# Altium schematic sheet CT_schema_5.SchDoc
size 278 x 170 mm
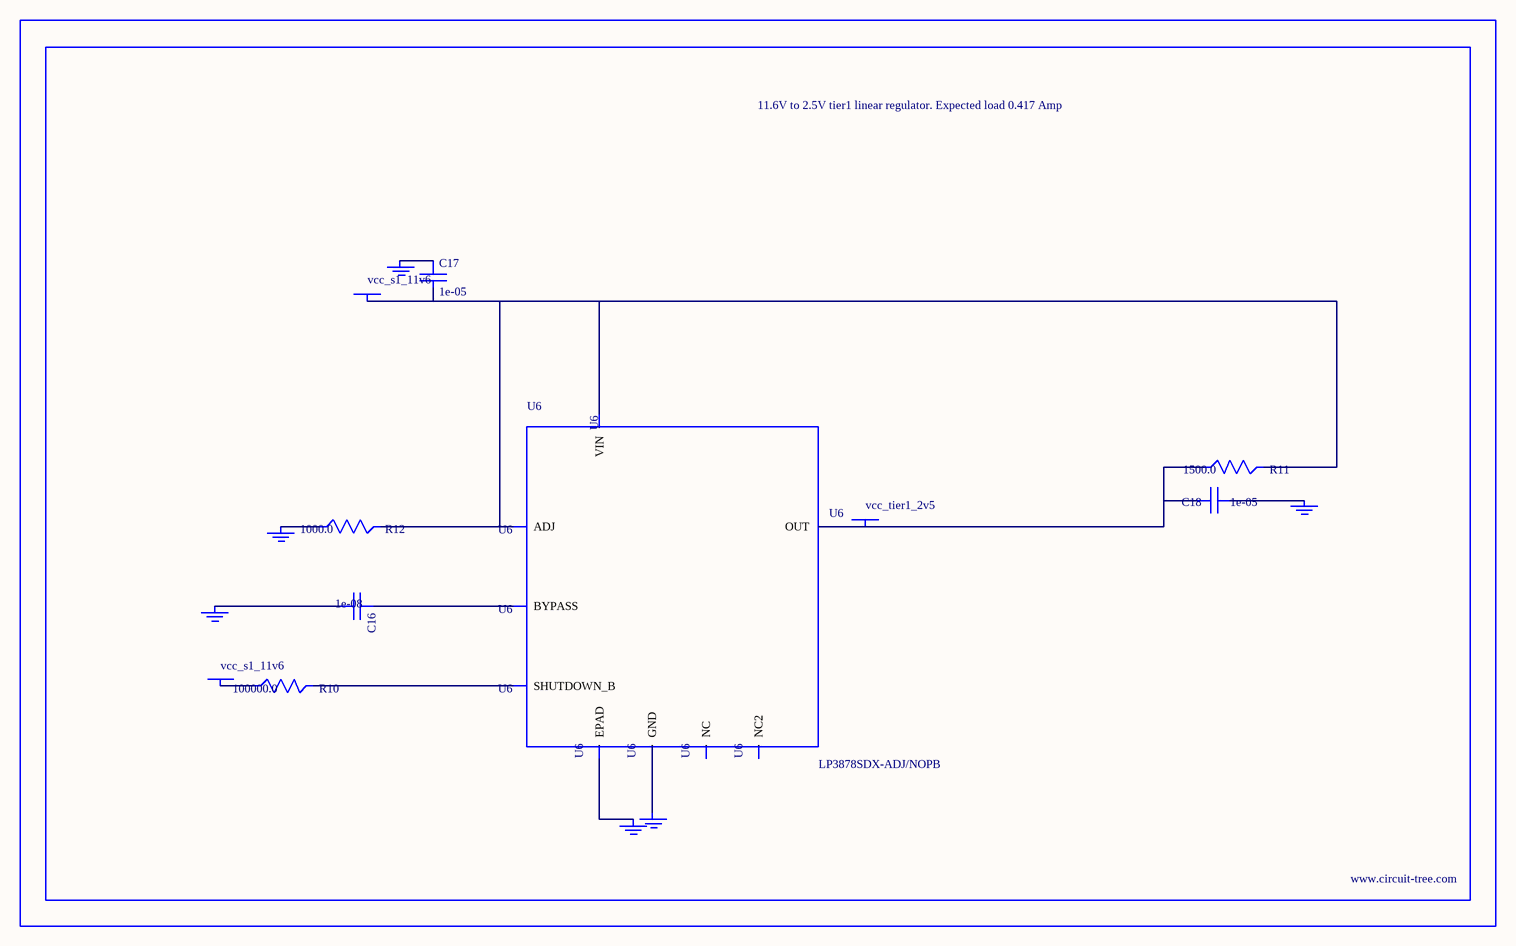
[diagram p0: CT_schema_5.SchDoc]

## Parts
BORDER4  (no value)
C16  1e-08  [C0402]
C17  1e-05  [C1210]
C18  1e-05  [C1210]
GND_INSTANCE_4_0  (no value)
GND_INSTANCE_4_1  (no value)
GND_INSTANCE_4_2  (no value)
GND_INSTANCE_4_3  (no value)
GND_INSTANCE_4_4  (no value)
GND_INSTANCE_4_5  (no value)
POWER_INSTANCE_4_0  vcc_s1_11v6
POWER_INSTANCE_4_1  vcc_s1_11v6
POWER_INSTANCE_4_2  vcc_tier1_2v5
R10  100000.0  [R0603]
R11  1500.0  [R0603]
R12  1000.0  [R0603]
U6  LP3878SDX-ADJ/NOPB  [WSON-8]

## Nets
NetC16_1: C16.1 U6.1(BYPASS)
NetC16_2: C16.2 GND_INSTANCE_4_0.0(GND)
NetC17_1: C17.1 GND_INSTANCE_4_1.0(GND)
NetC17_2: C17.2 POWER_INSTANCE_4_0.0(PWR) R11.2 R12.2 U6.4(VIN) U6.6(ADJ)
NetC18_1: C18.1 GND_INSTANCE_4_2.0(GND)
NetC18_2: C18.2 POWER_INSTANCE_4_2.0(PWR) R11.1 U6.5(OUT)
NetGND_INSTANCE_4_3_0: GND_INSTANCE_4_3.0(GND) R12.1
NetGND_INSTANCE_4_4_0: GND_INSTANCE_4_4.0(GND) U6.PAD(EPAD)
NetGND_INSTANCE_4_5_0: GND_INSTANCE_4_5.0(GND) U6.3(GND)
NetPOWER_INSTANCE_4_1_0: POWER_INSTANCE_4_1.0(PWR) R10.1
NetR10_2: R10.2 U6.8(SHUTDOWN_B)

Not connected (* = marked no-connect by the designer): U6 2(NC) 7(NC2)

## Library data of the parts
BORDER4 = BORDER_PAGE4
C16 = C0402C103K3RAC
C17 = C1210C106K5PACTU
C18 = GRM32DR61E106MA12L
GND_INSTANCE_4_0-GND_INSTANCE_4_5 = GND
POWER_INSTANCE_4_0-POWER_INSTANCE_4_2 = PWR
R10 = RC0603JR-07100KL
R11 = RC0603JR-071K5L
R12 = RC0603JR-071KL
